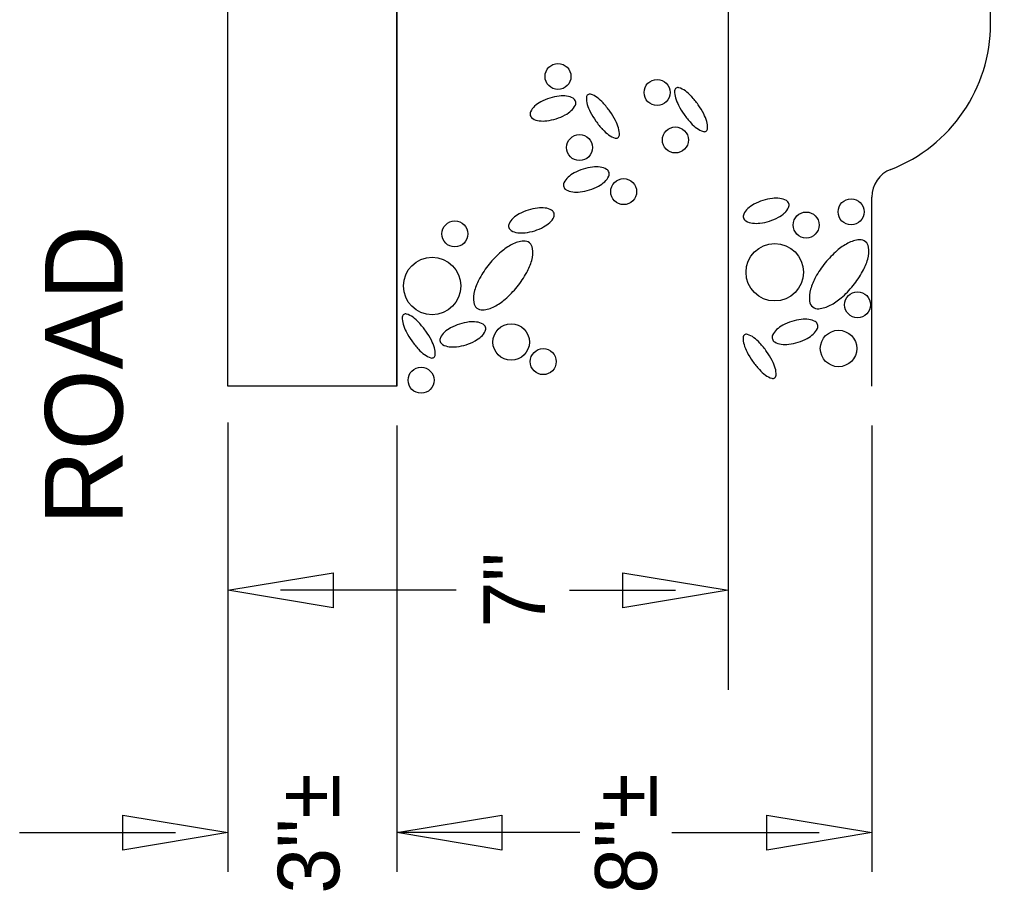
# Model space of a CAD drawing. Extents: x 0 to 8.5, y 0 to 11.
# Drawn here: x 4.657 to 5.603, y 6.567 to 7.415 of the extents above; entities that cross this region are included whole.
import ezdxf

# ---------------------------------------------------------------- set-up
doc = ezdxf.new("R2010")
doc.units = 0
for name, color, linetype in [('Default', 7, 'Continuous'), ('DTL-ASPHALT', 7, 'Continuous'), ('DTL-CONCRETE', 7, 'Continuous'), ('DTL-GRAVEL', 7, 'Continuous'), ('DTL-TEXT', 7, 'Continuous'), ('Old_Level_11', 7, 'Continuous')]:
    doc.layers.add(name, color=color, linetype=linetype)

# ---------------------------------------------------------------- blocks, each defined once
blk = doc.blocks.new('POINT_DISPLAY')
at = {"layer": 'Default'}
blk.add_line((0, 0), (0, 0), dxfattribs=at)

msp = doc.modelspace()

# ---------------------------------------------------------------- linework, layer by layer
at = {"layer": 'DTL-ASPHALT'}
msp.add_lwpolyline([(5.02444, 7.05788), (4.86007, 7.05788), (4.86007, 7.63621), (5.02444, 7.63621)], close=True, dxfattribs=at)
at = {"layer": 'DTL-CONCRETE'}
for p, q in [((4.86007, 7.05788), (4.86007, 8.71374)), ((5.02444, 7.05788), (5.02444, 7.63621))]:
    msp.add_line(p, q, dxfattribs=at)
at = {"layer": 'DTL-GRAVEL'}
for centre, radius in [((5.18147, 7.35946), 0.01265), ((5.27799, 7.34385), 0.01265), ((5.20245, 7.29021), 0.01265), ((5.29579, 7.29762), 0.01265), ((5.24543, 7.24729), 0.01265), ((5.46692, 7.22764), 0.01265), ((5.42315, 7.21477), 0.01265), ((5.08104, 7.20613), 0.01265), ((5.39258, 7.16877), 0.02797), ((5.0589, 7.1554), 0.02797), ((5.47321, 7.13707), 0.01265), ((5.13585, 7.10084), 0.01775), ((5.45471, 7.09451), 0.01775), ((5.16713, 7.08173), 0.01265), ((5.04814, 7.0636), 0.01265)]:
    msp.add_circle(centre, radius, dxfattribs=at)
for centre, radius, start, end in [((5.18866, 7.29014), 0.05062, 96.89302, 107.58263), ((5.18623, 7.31023), 0.03039, 83.08307, 96.89302), ((5.18788, 7.32384), 0.01667, 59.85119, 83.08307), ((5.21234, 7.33901), 0.00323, 125.09646, 176.96398), ((5.21234, 7.33901), 0.00323, 73.22894, 125.09646), ((5.20742, 7.32269), 0.02028, 53.10914, 73.22894), ((5.31531, 7.34454), 0.02028, 176.96398, 197.08379), ((5.29829, 7.34545), 0.00323, 125.09646, 176.96398), ((5.29829, 7.34545), 0.00323, 73.22894, 125.09646), ((5.29338, 7.32913), 0.02028, 53.10914, 73.22894), ((5.27959, 7.31076), 0.04324, 42.76732, 53.10914), ((5.25371, 7.28682), 0.0785, 35.09646, 42.76732), ((5.16988, 7.31814), 0.01667, 132.08218, 155.31406), ((5.17907, 7.30796), 0.03039, 118.27223, 132.08218), ((5.18866, 7.29014), 0.05062, 107.58263, 118.27223), ((5.18322, 7.33855), 0.01667, 312.08218, 335.31406), ((5.19364, 7.33376), 0.0052, 17.58263, 59.85119), ((5.19364, 7.33376), 0.0052, 335.31406, 17.58263), ((5.22935, 7.33811), 0.02028, 176.96398, 197.08379), ((5.2513, 7.34485), 0.04324, 197.08379, 207.4256), ((5.19363, 7.30432), 0.04324, 42.76732, 53.10914), ((5.16775, 7.28038), 0.0785, 35.09646, 42.76732), ((5.33726, 7.35129), 0.04324, 197.08379, 207.4256), ((5.36856, 7.36753), 0.0785, 207.4256, 215.09646), ((5.25371, 7.28682), 0.0785, 27.4256, 35.09646), ((5.15946, 7.32293), 0.0052, 155.31406, 197.58263), ((5.15946, 7.32293), 0.0052, 197.58263, 239.85119), ((5.16444, 7.36655), 0.05062, 287.58263, 298.27223), ((5.17403, 7.34873), 0.03039, 298.27223, 312.08218), ((5.2826, 7.36109), 0.0785, 207.4256, 215.09646), ((5.16775, 7.28038), 0.0785, 27.4256, 35.09646), ((5.36856, 7.36753), 0.0785, 215.09646, 222.76732), ((5.285, 7.30306), 0.04324, 17.08379, 27.4256), ((5.16522, 7.33285), 0.01667, 239.85119, 263.08307), ((5.16687, 7.34647), 0.03039, 263.08307, 276.89302), ((5.16444, 7.36655), 0.05062, 276.89302, 287.58263), ((5.2826, 7.36109), 0.0785, 215.09646, 222.76732), ((5.19905, 7.29662), 0.04324, 17.08379, 27.4256), ((5.34267, 7.34359), 0.04324, 222.76732, 233.10914), ((5.30695, 7.30981), 0.02028, 356.96398, 17.08379), ((5.25672, 7.33715), 0.04324, 222.76732, 233.10914), ((5.24293, 7.31878), 0.02028, 233.10914, 253.22894), ((5.23801, 7.30247), 0.00323, 305.09646, 356.96398), ((5.22099, 7.30337), 0.02028, 356.96398, 17.08379), ((5.32889, 7.32522), 0.02028, 233.10914, 253.22894), ((5.32397, 7.3089), 0.00323, 253.22894, 305.09646), ((5.32397, 7.3089), 0.00323, 305.09646, 356.96398), ((5.23801, 7.30247), 0.00323, 253.22894, 305.09646), ((5.21164, 7.2387), 0.03039, 118.27223, 132.08218), ((5.22122, 7.22089), 0.05062, 107.58263, 118.27223), ((5.22122, 7.22089), 0.05062, 96.89302, 107.58263), ((5.21879, 7.24097), 0.03039, 83.08307, 96.89302), ((5.22044, 7.25459), 0.01667, 59.85119, 83.08307), ((5.2262, 7.26451), 0.0052, 17.58263, 59.85119), ((5.2262, 7.26451), 0.0052, 335.31406, 17.58263), ((5.19202, 7.25367), 0.0052, 155.31406, 197.58263), ((5.20244, 7.24888), 0.01667, 132.08218, 155.31406), ((5.20659, 7.27948), 0.03039, 298.27223, 312.08218), ((5.21578, 7.2693), 0.01667, 312.08218, 335.31406), ((5.19202, 7.25367), 0.0052, 197.58263, 239.85119), ((5.19778, 7.26359), 0.01667, 239.85119, 263.08307), ((5.19943, 7.27721), 0.03039, 263.08307, 276.89302), ((5.197, 7.2973), 0.05062, 276.89302, 287.58263), ((5.197, 7.2973), 0.05062, 287.58263, 298.27223), ((5.39632, 7.19045), 0.05062, 107.58263, 118.27223), ((5.39632, 7.19045), 0.05062, 96.89302, 107.58263), ((5.39389, 7.21054), 0.03039, 83.08307, 96.89302), ((5.39554, 7.22416), 0.01667, 59.85119, 83.08307), ((5.4013, 7.23407), 0.0052, 17.58263, 59.85119), ((5.4013, 7.23407), 0.0052, 335.31406, 17.58263), ((5.16767, 7.18109), 0.05062, 107.58263, 118.27223), ((5.16767, 7.18109), 0.05062, 96.89302, 107.58263), ((5.16525, 7.20117), 0.03039, 83.08307, 96.89302), ((5.1669, 7.21479), 0.01667, 59.85119, 83.08307), ((5.17266, 7.22471), 0.0052, 17.58263, 59.85119), ((5.17266, 7.22471), 0.0052, 335.31406, 17.58263), ((5.37754, 7.21845), 0.01667, 132.08218, 155.31406), ((5.38674, 7.20827), 0.03039, 118.27223, 132.08218), ((5.38169, 7.24905), 0.03039, 298.27223, 312.08218), ((5.39088, 7.23886), 0.01667, 312.08218, 335.31406), ((5.1489, 7.20909), 0.01667, 132.08218, 155.31406), ((5.15809, 7.19891), 0.03039, 118.27223, 132.08218), ((5.15304, 7.23968), 0.03039, 298.27223, 312.08218), ((5.16224, 7.2295), 0.01667, 312.08218, 335.31406), ((5.36712, 7.22324), 0.0052, 155.31406, 197.58263), ((5.36712, 7.22324), 0.0052, 197.58263, 239.85119), ((5.37288, 7.23316), 0.01667, 239.85119, 263.08307), ((5.37211, 7.26686), 0.05062, 276.89302, 287.58263), ((5.37211, 7.26686), 0.05062, 287.58263, 298.27223), ((5.13848, 7.21388), 0.0052, 155.31406, 197.58263), ((5.13848, 7.21388), 0.0052, 197.58263, 239.85119), ((5.14424, 7.2238), 0.01667, 239.85119, 263.08307), ((5.14589, 7.23741), 0.03039, 263.08307, 276.89302), ((5.14346, 7.2575), 0.05062, 276.89302, 287.58263), ((5.14346, 7.2575), 0.05062, 287.58263, 298.27223), ((5.37454, 7.24678), 0.03039, 263.08307, 276.89302), ((5.15048, 7.16962), 0.02969, 95.0094, 117.78613), ((5.14861, 7.19099), 0.00824, 50.98289, 95.0094), ((5.47767, 7.17079), 0.02969, 95.0094, 117.78613), ((5.4758, 7.19216), 0.00824, 50.98289, 95.0094), ((5.4758, 7.19216), 0.00824, 6.95637, 50.98289), ((5.18836, 7.11679), 0.09511, 130.91747, 140.98289), ((5.16274, 7.14636), 0.05598, 117.78613, 130.91747), ((5.14861, 7.19099), 0.00824, 6.95637, 50.98289), ((5.12732, 7.18839), 0.02969, 344.17965, 6.95637), ((5.51556, 7.11796), 0.09511, 130.91747, 140.98289), ((5.48993, 7.14753), 0.05598, 117.78613, 130.91747), ((5.45451, 7.18956), 0.02969, 344.17965, 6.95637), ((5.10202, 7.19556), 0.05598, 331.04831, 344.17965), ((5.42921, 7.19673), 0.05598, 331.04831, 344.17965), ((5.18836, 7.11679), 0.09511, 140.98289, 151.04831), ((5.51556, 7.11796), 0.09511, 140.98289, 151.04831), ((5.39497, 7.21567), 0.09511, 320.98289, 331.04831), ((5.15413, 7.13573), 0.05598, 151.04831, 164.17965), ((5.06778, 7.2145), 0.09511, 320.98289, 331.04831), ((5.48132, 7.1369), 0.05598, 151.04831, 164.17965), ((5.12883, 7.1429), 0.02969, 164.17965, 186.95637), ((5.06778, 7.2145), 0.09511, 310.91747, 320.98289), ((5.45602, 7.14407), 0.02969, 164.17965, 186.95637), ((5.39497, 7.21567), 0.09511, 310.91747, 320.98289), ((5.09341, 7.18493), 0.05598, 297.78613, 310.91747), ((5.4206, 7.1861), 0.05598, 297.78613, 310.91747), ((5.10754, 7.1403), 0.00824, 186.95637, 230.98289), ((5.10754, 7.1403), 0.00824, 230.98289, 275.0094), ((5.10566, 7.16167), 0.02969, 275.0094, 297.78613), ((5.43473, 7.14147), 0.00824, 186.95637, 230.98289), ((5.43473, 7.14147), 0.00824, 230.98289, 275.0094), ((5.43286, 7.16284), 0.02969, 275.0094, 297.78613), ((5.05005, 7.1241), 0.02028, 176.96398, 197.08379), ((5.03304, 7.125), 0.00323, 125.09646, 176.96398), ((5.03304, 7.125), 0.00323, 73.22894, 125.09646), ((5.02812, 7.10868), 0.02028, 53.10914, 73.22894), ((5.01433, 7.09032), 0.04324, 42.76732, 53.10914), ((5.42438, 7.07257), 0.05062, 96.89302, 107.58263), ((5.42195, 7.09266), 0.03039, 83.08307, 96.89302), ((5.4236, 7.10627), 0.01667, 59.85119, 83.08307), ((5.072, 7.13084), 0.04324, 197.08379, 207.4256), ((4.98845, 7.06638), 0.0785, 35.09646, 42.76732), ((5.09131, 7.0879), 0.03039, 118.27223, 132.08218), ((5.10089, 7.07008), 0.05062, 107.58263, 118.27223), ((5.10089, 7.07008), 0.05062, 96.89302, 107.58263), ((5.09847, 7.09016), 0.03039, 83.08307, 96.89302), ((5.10012, 7.10378), 0.01667, 59.85119, 83.08307), ((5.10588, 7.1137), 0.0052, 17.58263, 59.85119), ((5.10588, 7.1137), 0.0052, 335.31406, 17.58263), ((5.4056, 7.10057), 0.01667, 132.08218, 155.31406), ((5.4148, 7.09039), 0.03039, 118.27223, 132.08218), ((5.42438, 7.07257), 0.05062, 107.58263, 118.27223), ((5.41894, 7.12098), 0.01667, 312.08218, 335.31406), ((5.42936, 7.11619), 0.0052, 17.58263, 59.85119), ((5.42936, 7.11619), 0.0052, 335.31406, 17.58263), ((5.1033, 7.14708), 0.0785, 207.4256, 215.09646), ((4.98845, 7.06638), 0.0785, 27.4256, 35.09646), ((5.0717, 7.10287), 0.0052, 155.31406, 197.58263), ((5.08212, 7.09808), 0.01667, 132.08218, 155.31406), ((5.08626, 7.12867), 0.03039, 298.27223, 312.08218), ((5.09546, 7.11849), 0.01667, 312.08218, 335.31406), ((5.38202, 7.10424), 0.02028, 176.96398, 197.08379), ((5.365, 7.10514), 0.00323, 125.09646, 176.96398), ((5.365, 7.10514), 0.00323, 73.22894, 125.09646), ((5.36009, 7.08883), 0.02028, 53.10914, 73.22894), ((5.3463, 7.07046), 0.04324, 42.76732, 53.10914), ((5.39518, 7.10536), 0.0052, 155.31406, 197.58263), ((5.39518, 7.10536), 0.0052, 197.58263, 239.85119), ((5.40017, 7.14898), 0.05062, 287.58263, 298.27223), ((5.40975, 7.13116), 0.03039, 298.27223, 312.08218), ((5.1033, 7.14708), 0.0785, 215.09646, 222.76732), ((5.07742, 7.12314), 0.04324, 222.76732, 233.10914), ((5.01975, 7.08262), 0.04324, 17.08379, 27.4256), ((5.0417, 7.08936), 0.02028, 356.96398, 17.08379), ((5.0717, 7.10287), 0.0052, 197.58263, 239.85119), ((5.07746, 7.11279), 0.01667, 239.85119, 263.08307), ((5.07911, 7.1264), 0.03039, 263.08307, 276.89302), ((5.07668, 7.14649), 0.05062, 276.89302, 287.58263), ((5.07668, 7.14649), 0.05062, 287.58263, 298.27223), ((5.40397, 7.11099), 0.04324, 197.08379, 207.4256), ((5.32042, 7.04652), 0.0785, 35.09646, 42.76732), ((5.40094, 7.11528), 0.01667, 239.85119, 263.08307), ((5.40259, 7.1289), 0.03039, 263.08307, 276.89302), ((5.40017, 7.14898), 0.05062, 276.89302, 287.58263), ((5.06363, 7.10478), 0.02028, 233.10914, 253.22894), ((5.05871, 7.08846), 0.00323, 253.22894, 305.09646), ((5.05871, 7.08846), 0.00323, 305.09646, 356.96398), ((5.43527, 7.12723), 0.0785, 207.4256, 215.09646), ((5.32042, 7.04652), 0.0785, 27.4256, 35.09646), ((5.43527, 7.12723), 0.0785, 215.09646, 222.76732), ((5.35171, 7.06276), 0.04324, 17.08379, 27.4256), ((5.37366, 7.06951), 0.02028, 356.96398, 17.08379), ((5.40938, 7.10329), 0.04324, 222.76732, 233.10914), ((5.3956, 7.08492), 0.02028, 233.10914, 253.22894), ((5.39068, 7.0686), 0.00323, 253.22894, 305.09646), ((5.39068, 7.0686), 0.00323, 305.09646, 356.96398)]:
    msp.add_arc(centre, radius, start, end, dxfattribs=at)
at = {"layer": 'DTL-TEXT'}
for p, q in [((5.60277, 7.41091), (5.60277, 9.00365)), ((5.34709, 7.59781), (5.34709, 7.01948)), ((5.4871, 7.05788), (5.4871, 7.24203)), ((4.86007, 7.02245), (4.86007, 6.80968)), ((4.86007, 7.01948), (4.86007, 6.76218)), ((4.86007, 7.01948), (4.86007, 6.58468)), ((5.02444, 7.01948), (5.02444, 6.58468)), ((5.02444, 7.01948), (5.02444, 6.58468)), ((5.34709, 7.01948), (5.34709, 6.76218)), ((5.4871, 7.01948), (5.4871, 6.58468)), ((5.08226, 6.85909), (4.91127, 6.85909)), ((5.19276, 6.85909), (5.29589, 6.85909)), ((4.65694, 6.62308), (4.80887, 6.62308)), ((5.07564, 6.62308), (5.02444, 6.62308)), ((5.20278, 6.62308), (5.07564, 6.62308)), ((5.29238, 6.62308), (5.4359, 6.62308))]:
    msp.add_line(p, q, dxfattribs=at)
for points in [[(4.96247, 6.84202), (4.86007, 6.85909), (4.96247, 6.87615)], [(5.24469, 6.87615), (5.34709, 6.85909), (5.24469, 6.84202)], [(4.75767, 6.64015), (4.86007, 6.62308), (4.75767, 6.60602)], [(5.12684, 6.60602), (5.02444, 6.62308), (5.12684, 6.64015)], [(5.3847, 6.64015), (5.4871, 6.62308), (5.3847, 6.60602)]]:
    msp.add_lwpolyline(points, close=True, dxfattribs=at)
for centre, radius, start, end in [((5.45058, 7.41091), 0.15219, 291.18279, 0), ((5.51602, 7.24203), 0.02892, 111.18279, 180)]:
    msp.add_arc(centre, radius, start, end, dxfattribs=at)

# ---------------------------------------------------------------- block references
at = {"layer": 'DTL-CONCRETE', "xscale": 0.6400000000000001, "yscale": 0.6400000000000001, "rotation": 90}
for p in [(4.86007, 7.0605), (4.86007, 7.0605), (5.02444, 7.05788)]:
    msp.add_blockref('POINT_DISPLAY', p, dxfattribs=at)

# ---------------------------------------------------------------- texts
at = {"layer": 'DTL-TEXT'}
for s, p in [('7"', (5.16877, 6.82287)), ('3"±', (4.96852, 6.5635)), ('8"±', (5.27762, 6.5635))]:
    msp.add_text(s, height=0.06, rotation=90, dxfattribs=at).set_placement(p)
at = {"layer": 'Old_Level_11'}
msp.add_text('ROAD', height=0.0756, rotation=90, dxfattribs=at).set_placement((4.75745, 6.92248))

doc.saveas('drawing.dxf')
